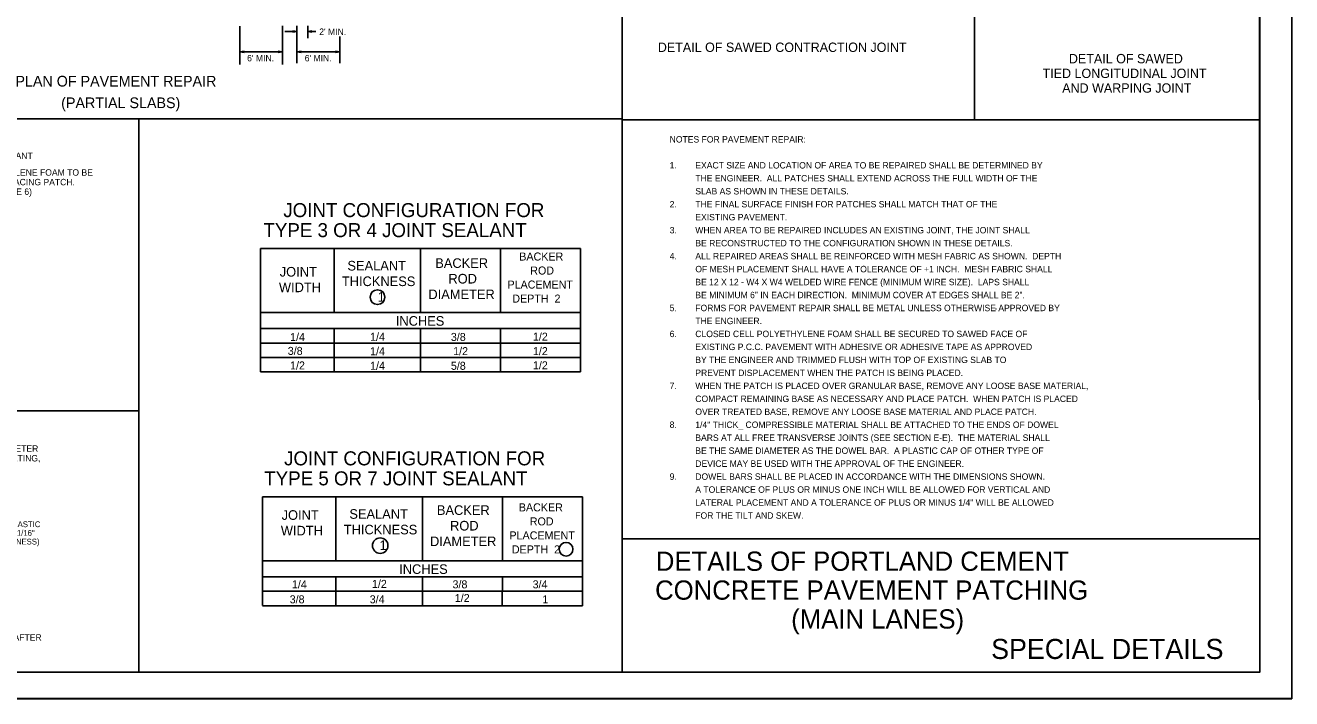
# Model space of a CAD drawing. Extents: x 1375738 to 1375905, y 380661 to 380875.
# Drawn here: x 1375810.1 to 1375904.9, y 380768.1 to 380818.4 of the extents above; entities that cross this region are included whole.
import ezdxf

# ---------------------------------------------------------------- set-up
doc = ezdxf.new("R2010")
doc.units = 0
for name, color, linetype in [('R_Border', 7, 'Continuous'), ('R_Draft', 7, 'Continuous'), ('R_No Plot', 7, 'Continuous')]:
    doc.layers.add(name, color=color, linetype=linetype)

msp = doc.modelspace()

# ---------------------------------------------------------------- linework, layer by layer
at = {"layer": 'R_Border'}
for p, q in [((1375854.78, 380770.053), (1375854.78, 380872.783)), ((1375902.509, 380770.053), (1375902.509, 380872.783)), ((1375881.145, 380811.354), (1375881.145, 380839.872)), ((1375786.095, 380811.429), (1375854.78, 380811.429)), ((1375818.592, 380770.053), (1375818.592, 380811.429)), ((1375854.78, 380811.354), (1375902.509, 380811.354)), ((1375786.095, 380789.583), (1375818.592, 380789.583)), ((1375854.78, 380780.008), (1375902.509, 380780.008)), ((1375902.509, 380770.053), (1375744.419, 380770.053))]:
    msp.add_line(p, q, dxfattribs=at)
at = {"layer": 'R_Draft'}
for p, q in [((1375826.149, 380818.375), (1375826.149, 380815.493)), ((1375829.349, 380818.389), (1375829.349, 380815.493)), ((1375829.531, 380817.97), (1375830.429, 380817.97)), ((1375830.109, 380818.018), (1375830.429, 380817.97)), ((1375830.109, 380818.018), (1375830.109, 380817.922)), ((1375830.109, 380818.01), (1375830.376, 380817.97)), ((1375830.109, 380818.002), (1375830.321, 380817.97)), ((1375830.109, 380817.994), (1375830.268, 380817.97)), ((1375830.109, 380817.986), (1375830.213, 380817.97)), ((1375830.109, 380817.978), (1375830.16, 380817.97)), ((1375830.109, 380817.922), (1375830.429, 380817.97)), ((1375830.109, 380817.955), (1375830.213, 380817.97)), ((1375830.109, 380817.938), (1375830.321, 380817.97)), ((1375830.109, 380817.93), (1375830.376, 380817.97)), ((1375830.109, 380817.946), (1375830.268, 380817.97)), ((1375830.109, 380817.963), (1375830.16, 380817.97)), ((1375830.429, 380818.403), (1375830.429, 380815.597)), ((1375831.229, 380818.403), (1375831.229, 380817.47)), ((1375831.549, 380818.018), (1375831.229, 380817.97)), ((1375831.229, 380817.97), (1375831.842, 380817.97)), ((1375831.549, 380817.922), (1375831.229, 380817.97)), ((1375831.549, 380818.01), (1375831.283, 380817.97)), ((1375831.549, 380817.93), (1375831.283, 380817.97)), ((1375831.549, 380818.002), (1375831.338, 380817.97)), ((1375831.549, 380817.938), (1375831.338, 380817.97)), ((1375831.549, 380817.994), (1375831.391, 380817.97)), ((1375831.549, 380817.946), (1375831.391, 380817.97)), ((1375831.549, 380817.986), (1375831.445, 380817.97)), ((1375831.549, 380817.955), (1375831.445, 380817.97)), ((1375831.549, 380817.978), (1375831.499, 380817.97)), ((1375831.549, 380817.963), (1375831.499, 380817.97)), ((1375831.549, 380817.922), (1375831.549, 380818.018)), ((1375833.629, 380817.609), (1375833.629, 380815.597)), ((1375826.469, 380816.505), (1375826.149, 380816.457)), ((1375829.349, 380816.457), (1375826.149, 380816.457)), ((1375826.469, 380816.409), (1375826.149, 380816.457)), ((1375826.469, 380816.497), (1375826.203, 380816.457)), ((1375826.469, 380816.417), (1375826.203, 380816.457)), ((1375826.469, 380816.489), (1375826.258, 380816.457)), ((1375826.469, 380816.425), (1375826.258, 380816.457)), ((1375826.469, 380816.481), (1375826.311, 380816.457)), ((1375826.469, 380816.433), (1375826.311, 380816.457)), ((1375826.469, 380816.472), (1375826.365, 380816.457)), ((1375826.469, 380816.441), (1375826.365, 380816.457)), ((1375826.469, 380816.464), (1375826.419, 380816.457)), ((1375826.469, 380816.449), (1375826.419, 380816.457)), ((1375826.469, 380816.409), (1375826.469, 380816.505)), ((1375829.029, 380816.505), (1375829.349, 380816.457)), ((1375829.029, 380816.505), (1375829.029, 380816.409)), ((1375829.029, 380816.497), (1375829.296, 380816.457)), ((1375829.029, 380816.489), (1375829.241, 380816.457)), ((1375829.029, 380816.481), (1375829.188, 380816.457)), ((1375829.029, 380816.472), (1375829.133, 380816.457)), ((1375829.029, 380816.464), (1375829.08, 380816.457)), ((1375829.029, 380816.409), (1375829.349, 380816.457)), ((1375829.029, 380816.441), (1375829.133, 380816.457)), ((1375829.029, 380816.425), (1375829.241, 380816.457)), ((1375829.029, 380816.417), (1375829.296, 380816.457)), ((1375829.029, 380816.433), (1375829.188, 380816.457)), ((1375829.029, 380816.449), (1375829.08, 380816.457)), ((1375830.749, 380816.505), (1375830.429, 380816.457)), ((1375833.629, 380816.457), (1375830.429, 380816.457)), ((1375830.749, 380816.409), (1375830.429, 380816.457)), ((1375830.749, 380816.497), (1375830.483, 380816.457)), ((1375830.749, 380816.417), (1375830.483, 380816.457)), ((1375830.749, 380816.489), (1375830.538, 380816.457)), ((1375830.749, 380816.425), (1375830.538, 380816.457)), ((1375830.749, 380816.481), (1375830.591, 380816.457)), ((1375830.749, 380816.433), (1375830.591, 380816.457)), ((1375830.749, 380816.472), (1375830.645, 380816.457)), ((1375830.749, 380816.441), (1375830.645, 380816.457)), ((1375830.749, 380816.464), (1375830.699, 380816.457)), ((1375830.749, 380816.449), (1375830.699, 380816.457)), ((1375830.749, 380816.409), (1375830.749, 380816.505)), ((1375833.309, 380816.505), (1375833.629, 380816.457)), ((1375833.309, 380816.505), (1375833.309, 380816.409)), ((1375833.309, 380816.497), (1375833.576, 380816.457)), ((1375833.309, 380816.489), (1375833.521, 380816.457)), ((1375833.309, 380816.481), (1375833.468, 380816.457)), ((1375833.309, 380816.472), (1375833.413, 380816.457)), ((1375833.309, 380816.464), (1375833.36, 380816.457)), ((1375833.309, 380816.409), (1375833.629, 380816.457)), ((1375833.309, 380816.441), (1375833.413, 380816.457)), ((1375833.309, 380816.425), (1375833.521, 380816.457)), ((1375833.309, 380816.417), (1375833.576, 380816.457)), ((1375833.309, 380816.433), (1375833.468, 380816.457)), ((1375833.309, 380816.449), (1375833.36, 380816.457)), ((1375827.696, 380792.507), (1375827.696, 380801.73)), ((1375827.696, 380801.73), (1375851.654, 380801.73)), ((1375833.205, 380801.728), (1375833.205, 380796.939)), ((1375839.675, 380801.728), (1375839.675, 380796.939)), ((1375845.664, 380801.728), (1375845.664, 380796.939)), ((1375851.654, 380801.728), (1375851.654, 380792.507)), ((1375827.696, 380796.939), (1375851.654, 380796.939)), ((1375833.685, 380795.741), (1375827.696, 380795.741)), ((1375833.205, 380794.663), (1375833.205, 380795.741)), ((1375839.675, 380795.741), (1375833.685, 380795.741)), ((1375845.664, 380795.741), (1375839.675, 380795.741)), ((1375839.675, 380794.663), (1375839.675, 380795.741)), ((1375851.654, 380795.741), (1375845.664, 380795.741)), ((1375845.664, 380794.663), (1375845.664, 380795.741)), ((1375851.654, 380794.663), (1375851.654, 380795.741)), ((1375827.696, 380794.663), (1375833.205, 380794.663)), ((1375833.205, 380794.663), (1375839.675, 380794.663)), ((1375833.205, 380793.585), (1375833.205, 380794.663)), ((1375839.675, 380794.663), (1375845.664, 380794.663)), ((1375839.675, 380793.585), (1375839.675, 380794.663)), ((1375845.664, 380794.663), (1375851.654, 380794.663)), ((1375845.664, 380793.585), (1375845.664, 380794.663)), ((1375851.654, 380793.585), (1375851.654, 380794.663)), ((1375827.696, 380793.585), (1375833.205, 380793.585)), ((1375833.205, 380793.585), (1375839.675, 380793.585)), ((1375833.205, 380792.507), (1375833.205, 380793.585)), ((1375839.675, 380793.585), (1375845.664, 380793.585)), ((1375839.675, 380792.507), (1375839.675, 380793.585)), ((1375845.664, 380793.585), (1375851.654, 380793.585)), ((1375845.664, 380792.507), (1375845.664, 380793.585)), ((1375851.654, 380792.507), (1375851.654, 380793.585)), ((1375827.696, 380792.507), (1375833.205, 380792.507)), ((1375833.205, 380792.507), (1375839.675, 380792.507)), ((1375839.675, 380792.507), (1375845.664, 380792.507)), ((1375845.664, 380792.507), (1375851.654, 380792.507)), ((1375827.853, 380783.161), (1375851.811, 380783.161)), ((1375827.853, 380775.031), (1375827.853, 380783.161)), ((1375833.334, 380783.158), (1375833.334, 380778.369)), ((1375839.832, 380783.158), (1375839.832, 380778.369)), ((1375845.821, 380783.158), (1375845.821, 380778.369)), ((1375851.811, 380783.158), (1375851.811, 380777.171)), ((1375827.853, 380778.369), (1375851.811, 380778.369)), ((1375833.842, 380777.171), (1375827.853, 380777.171)), ((1375833.334, 380776.093), (1375833.334, 380777.171)), ((1375839.832, 380777.171), (1375833.842, 380777.171)), ((1375845.821, 380777.171), (1375839.832, 380777.171)), ((1375839.832, 380776.093), (1375839.832, 380777.171)), ((1375851.811, 380777.171), (1375845.821, 380777.171)), ((1375845.821, 380776.093), (1375845.821, 380777.171)), ((1375851.811, 380776.093), (1375851.811, 380777.171)), ((1375827.853, 380776.093), (1375833.334, 380776.093)), ((1375833.334, 380776.093), (1375839.832, 380776.093)), ((1375833.334, 380775.015), (1375833.334, 380776.093)), ((1375839.832, 380776.093), (1375845.821, 380776.093)), ((1375839.832, 380775.015), (1375839.832, 380776.093)), ((1375845.796, 380775.015), (1375845.796, 380776.093)), ((1375845.821, 380776.093), (1375851.811, 380776.093)), ((1375851.793, 380775.015), (1375851.793, 380776.093)), ((1375851.811, 380775.015), (1375827.853, 380775.015)), ((1375827.853, 380775.014), (1375827.853, 380775.015)), ((1375827.853, 380775.015), (1375833.334, 380775.015)), ((1375839.807, 380775.015), (1375845.796, 380775.015)), ((1375845.804, 380775.015), (1375851.793, 380775.015))]:
    msp.add_line(p, q, dxfattribs=at)
for centre, radius in [((1375836.455, 380798.098), 0.554), ((1375836.659, 380779.509), 0.58), ((1375850.573, 380779.237), 0.512)]:
    msp.add_circle(centre, radius, dxfattribs=at)
at = {"layer": 'R_No Plot'}
msp.add_line((1375738.219, 380768.063), (1375904.885, 380768.063), dxfattribs=at)
for points in [[(1375738.215, 380874.73), (1375904.885, 380874.73), (1375904.885, 380768.061), (1375738.215, 380768.061)], [(1375861.379, 380872.783), (1375871.189, 380872.783), (1375871.189, 380867.843), (1375879.245, 380867.843), (1375890.845, 380867.843), (1375890.845, 380851.508), (1375902.449, 380851.508), (1375902.509, 380770.053), (1375744.419, 380770.053), (1375744.419, 380872.783)]]:
    msp.add_lwpolyline(points, close=True, dxfattribs=at)

# ---------------------------------------------------------------- texts
at = {"layer": 'R_Border'}
msp.add_text('SPECIAL DETAILS', height=1.5, dxfattribs=at).set_placement((1375882.391, 380771.032))
at = {"layer": 'R_Draft'}
for s, height, p in [("2' MIN.", 0.48, (1375832.094, 380817.715)), ('DETAIL OF SAWED CONTRACTION JOINT', 0.7, (1375857.44, 380816.443)), ("6' MIN.", 0.48, (1375826.697, 380815.737)), ("6' MIN.", 0.48, (1375831.005, 380815.737)), ('DETAIL OF SAWED ', 0.7, (1375888.211, 380815.592)), ('TIED LONGITUDINAL JOINT ', 0.7, (1375886.238, 380814.492)), ('PLAN OF PAVEMENT REPAIR', 0.8, (1375809.354, 380813.855)), ('AND WARPING JOINT', 0.7, (1375887.709, 380813.392)), ('(PARTIAL SLABS)', 0.8, (1375812.777, 380812.238)), ('NOTES FOR PAVEMENT REPAIR:', 0.48, (1375858.325, 380809.664)), ('SAWED JOINT AND JOINT SEALANT', 0.48, (1375799.594, 380808.431)), ('1.', 0.48, (1375858.325, 380807.723)), ('EXACT SIZE AND LOCATION OF AREA TO BE REPAIRED SHALL BE DETERMINED BY', 0.48, (1375860.245, 380807.723)), ('1/4" CLOSED CELL POLYETHYLENE FOAM TO BE', 0.48, (1375800.013, 380807.187)), ('THE ENGINEER.  ALL PATCHES SHALL EXTEND ACROSS THE FULL WIDTH OF THE', 0.48, (1375860.245, 380806.753)), ('PLACED PRIOR TO PLACING PATCH.', 0.48, (1375802.428, 380806.467)), ('(SEE NOTE 6)', 0.48, (1375806.382, 380805.747)), ('SLAB AS SHOWN IN THESE DETAILS.', 0.48, (1375860.245, 380805.782)), ('JOINT CONFIGURATION FOR', 1.04816, (1375829.404, 380804.085)), ('2.', 0.48, (1375858.325, 380804.812)), ('THE FINAL SURFACE FINISH FOR PATCHES SHALL MATCH THAT OF THE', 0.48, (1375860.245, 380804.812)), ('TYPE 3 OR 4 JOINT SEALANT', 1.04816, (1375827.918, 380802.588)), ('EXISTING PAVEMENT.', 0.48, (1375860.245, 380803.842)), ('3.', 0.48, (1375858.325, 380802.871)), ('WHEN AREA TO BE REPAIRED INCLUDES AN EXISTING JOINT, THE JOINT SHALL', 0.48, (1375860.245, 380802.871)), ('BE RECONSTRUCTED TO THE CONFIGURATION SHOWN IN THESE DETAILS.', 0.48, (1375860.245, 380801.901)), ('SEALANT', 0.7187, (1375834.206, 380800.093)), ('BACKER', 0.7187, (1375840.78, 380800.286)), ('BACKER', 0.599, (1375847.069, 380800.838)), ('4.', 0.48, (1375858.325, 380800.93)), ('ALL REPAIRED AREAS SHALL BE REINFORCED WITH MESH FABRIC AS SHOWN.  DEPTH', 0.48, (1375860.245, 380800.93)), ('JOINT', 0.7187, (1375829.138, 380799.638)), ('THICKNESS', 0.7187, (1375833.79, 380798.926)), ('ROD', 0.7187, (1375841.765, 380799.119)), ('ROD', 0.599, (1375847.89, 380799.79)), ('OF MESH PLACEMENT SHALL HAVE A TOLERANCE OF +1 INCH.  MESH FABRIC SHALL ', 0.48, (1375860.245, 380799.96)), ('WIDTH', 0.7187, (1375829.078, 380798.471)), ('PLACEMENT', 0.599, (1375846.188, 380798.741)), ('BE 12 X 12 - W4 X W4 WELDED WIRE FENCE (MINIMUM WIRE SIZE).  LAPS SHALL', 0.48, (1375860.245, 380798.99)), ('1', 0.719, (1375836.467, 380797.758)), ('DIAMETER', 0.7187, (1375840.265, 380797.951)), ('DEPTH  2', 0.599, (1375846.548, 380797.693)), ('BE MINIMUM 6" IN EACH DIRECTION.  MINIMUM COVER AT EDGES SHALL BE 2".', 0.48, (1375860.245, 380798.019)), ('5.', 0.48, (1375858.325, 380797.049)), ('FORMS FOR PAVEMENT REPAIR SHALL BE METAL UNLESS OTHERWISE APPROVED BY', 0.48, (1375860.245, 380797.049)), ('-', 0.48, (1375882.644, 380797.024)), ('INCHES', 0.7187, (1375837.826, 380795.961)), ('THE ENGINEER.', 0.48, (1375860.245, 380796.078)), ('1/4', 0.599, (1375829.911, 380794.816)), ('1/4', 0.599, (1375835.9, 380794.834)), ('3/8', 0.599, (1375841.948, 380794.822)), ('1/2', 0.599, (1375848.09, 380794.842)), ('6.', 0.48, (1375858.325, 380795.108)), ('CLOSED CELL POLYETHYLENE FOAM SHALL BE SECURED TO SAWED FACE OF', 0.48, (1375860.245, 380795.108)), ('3/8', 0.599, (1375829.739, 380793.778)), ('1/4', 0.599, (1375835.9, 380793.755)), ('1/2', 0.599, (1375842.118, 380793.759)), ('1/2', 0.599, (1375848.09, 380793.762)), ('EXISTING P.C.C. PAVEMENT WITH ADHESIVE OR ADHESIVE TAPE AS APPROVED', 0.48, (1375860.245, 380794.138)), ('1/2', 0.599, (1375829.909, 380792.69)), ('1/4', 0.599, (1375835.9, 380792.667)), ('5/8', 0.599, (1375841.948, 380792.663)), ('1/2', 0.599, (1375848.09, 380792.698)), ('BY THE ENGINEER AND TRIMMED FLUSH WITH TOP OF EXISTING SLAB TO ', 0.48, (1375860.245, 380793.167)), ('PREVENT DISPLACEMENT WHEN THE PATCH IS BEING PLACED.', 0.48, (1375860.245, 380792.197)), ('7.', 0.48, (1375858.325, 380791.226)), ('WHEN THE PATCH IS PLACED OVER GRANULAR BASE, REMOVE ANY LOOSE BASE MATERIAL,', 0.48, (1375860.245, 380791.226)), ('COMPACT REMAINING BASE AS NECESSARY AND PLACE PATCH.  WHEN PATCH IS PLACED', 0.48, (1375860.245, 380790.256)), ('OVER TREATED BASE, REMOVE ANY LOOSE BASE MATERIAL AND PLACE PATCH.', 0.48, (1375860.245, 380789.286)), ('8.', 0.48, (1375858.325, 380788.315)), ('1/4" THICK_ COMPRESSIBLE MATERIAL SHALL BE ATTACHED TO THE ENDS OF DOWEL', 0.48, (1375860.245, 380788.315)), ('BARS AT ALL FREE TRANSVERSE JOINTS (SEE SECTION E-E).  THE MATERIAL SHALL', 0.48, (1375860.245, 380787.345)), ('D=DOWEL DIAMETER', 0.48, (1375804.379, 380786.527)), ('JOINT CONFIGURATION FOR', 1.04816, (1375829.464, 380785.516)), ('BE THE SAME DIAMETER AS THE DOWEL BAR.  A PLASTIC CAP OF OTHER TYPE OF ', 0.48, (1375860.245, 380786.374)), ('(INCLUDING COATING,', 0.48, (1375804.196, 380785.807)), ('DEVICE MAY BE USED WITH THE APPROVAL OF THE ENGINEER.', 0.48, (1375860.245, 380785.404)), ('TYPE 5 OR 7 JOINT SEALANT', 1.04816, (1375827.978, 380784.019)), ('9.', 0.48, (1375858.325, 380784.434)), ('DOWEL BARS SHALL BE PLACED IN ACCORDANCE WITH THE DIMENSIONS SHOWN.', 0.48, (1375860.245, 380784.434)), ('A TOLERANCE OF PLUS OR MINUS ONE INCH WILL BE ALLOWED FOR VERTICAL AND', 0.48, (1375860.245, 380783.463)), ('BACKER', 0.599, (1375847.035, 380782.073)), ('LATERAL PLACEMENT AND A TOLERANCE OF PLUS OR MINUS 1/4" WILL BE ALLOWED', 0.48, (1375860.245, 380782.493)), ('JOINT', 0.7187, (1375829.28, 380781.44)), ('SEALANT', 0.7187, (1375834.349, 380781.518)), ('BACKER', 0.7187, (1375840.902, 380781.809)), ('ROD', 0.599, (1375847.856, 380781.025)), ('FOR THE TILT AND SKEW.', 0.48, (1375860.245, 380781.522)), ('NYLON OR PLASTIC', 0.432, (1375805.636, 380780.892)), ('MATERIAL (1/16"', 0.432, (1375806.221, 380780.244)), ('WIDTH', 0.7187, (1375829.221, 380780.273)), ('THICKNESS', 0.7187, (1375833.933, 380780.351)), ('ROD', 0.7187, (1375841.887, 380780.641)), ('MIN. THICKNESS)', 0.432, (1375806.278, 380779.596)), ('1', 0.719, (1375836.61, 380779.183)), ('DIAMETER', 0.7187, (1375840.387, 380779.474)), ('PLACEMENT', 0.599, (1375846.334, 380779.976)), ('DEPTH  2', 0.599, (1375846.514, 380778.928)), ('DETAILS OF PORTLAND CEMENT', 1.44, (1375857.29, 380777.625)), ('INCHES', 0.7187, (1375838.08, 380777.393)), ('1/4', 0.599, (1375830.053, 380776.315)), ('1/2', 0.599, (1375836.041, 380776.347)), ('3/8', 0.599, (1375842.071, 380776.314)), ('3/4', 0.599, (1375848.067, 380776.315)), ('CONCRETE PAVEMENT PATCHING', 1.44, (1375857.234, 380775.465)), ('3/8', 0.599, (1375829.882, 380775.194)), ('3/4', 0.599, (1375835.873, 380775.196)), ('1/2', 0.599, (1375842.24, 380775.291)), ('1', 0.599, (1375848.798, 380775.195)), ('(MAIN LANES)', 1.44, (1375867.421, 380773.305)), (' OVER TIE BARS AND FIRMLY AGAINST THE SLAB FACE AFTER', 0.48, (1375791.701, 380772.401))]:
    msp.add_text(s, height=height, dxfattribs=at).set_placement(p)

doc.saveas('drawing.dxf')
